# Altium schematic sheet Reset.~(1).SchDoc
size A4
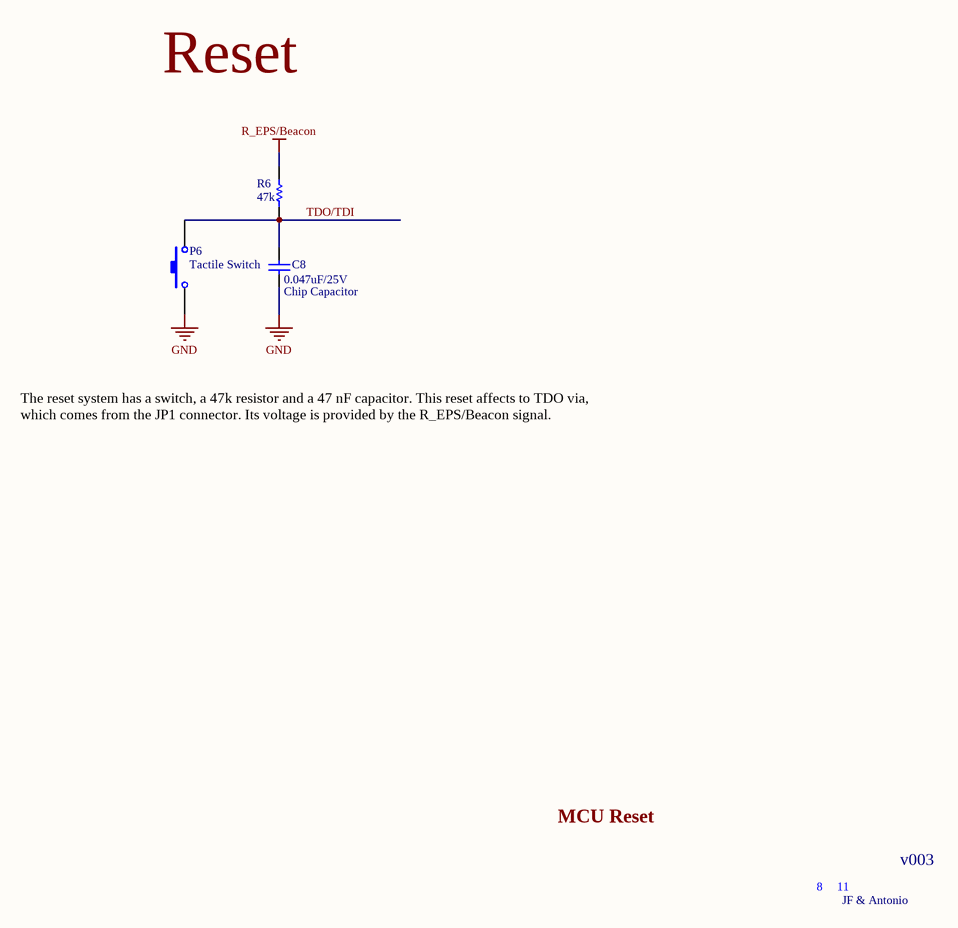
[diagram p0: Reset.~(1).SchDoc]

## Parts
C8  value 0.047uF/25V  PackageDescription: Chip Capacitor  [C0.047u]
P6  Tactile Switch  [SPST-2]
R6  47k  [R47k]

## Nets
GND: C8.2 P6.1
R_EPS/Beacon: R6.2
TDO/TDI: C8.1 P6.2 R6.1

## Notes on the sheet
- Reset
- The reset system has a switch, a 47k resistor and a 47 nF capacitor. This reset affects to TDO via, which comes from the JP1 connector. Its voltage is provided by the R_EPS/Beacon signal.
- MCU Reset
- 8
- 11
- v003
- JF & Antonio

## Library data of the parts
C8 = Cap Semi: Capacitor (Semiconductor SIM Model)
P6 = SW-PB: Switch
R6 = Res1: Resistor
